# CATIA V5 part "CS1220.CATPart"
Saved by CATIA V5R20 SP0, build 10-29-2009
Part number: CS1220
Revision: 4
Definition: design
Nomenclature: CS1220
Source: made
Description: NOT SPECIFIED
Bounding box of the stored display mesh (mm): x -18.807 to 19, y -19 to 19, z -36 to 9
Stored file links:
  C:\Users\Raffaele\Desktop\3D X SITO CF\BOLEX\20-TILTED COLUMN SUPPORT\CS1220.CATPart
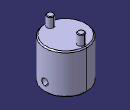
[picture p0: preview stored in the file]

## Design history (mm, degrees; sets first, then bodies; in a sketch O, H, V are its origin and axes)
Body1 "MANIFOLD_SOLID_BREP #695" (main body)
  Solid1: solid without history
